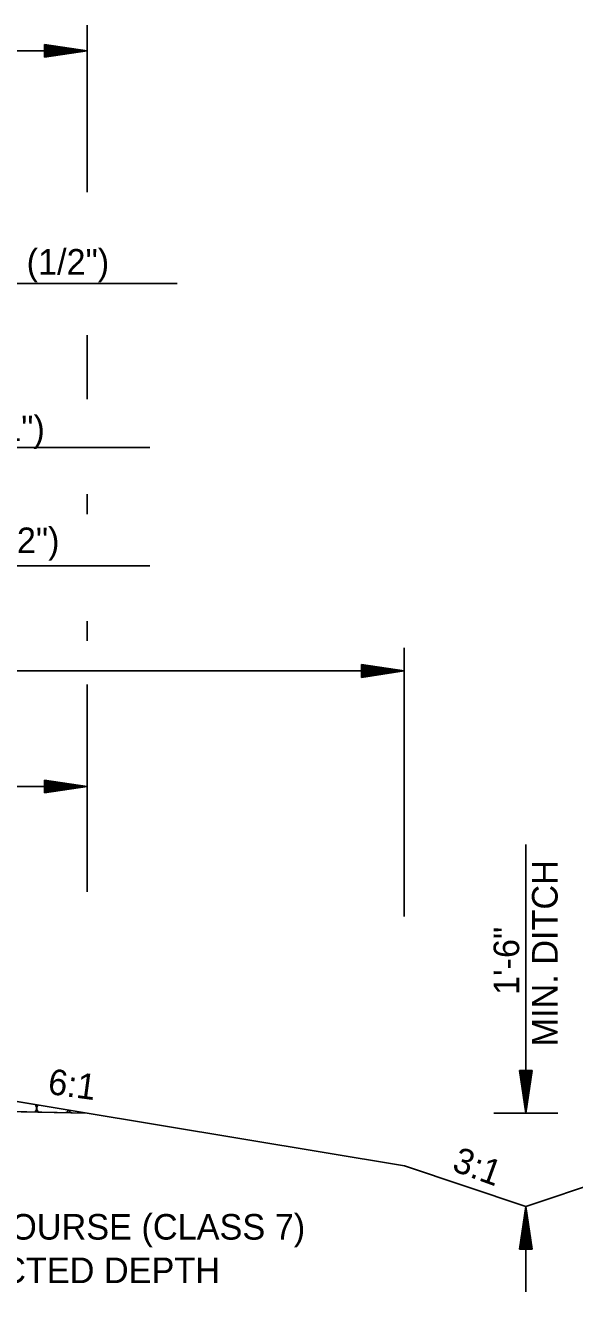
# Model space of a CAD drawing. Extents: x 1371763 to 1372860, y 385599 to 385872.
# Drawn here: x 1372116.52 to 1372129.38, y 385642.19 to 385671.88 of the extents above; entities that cross this region are included whole.
import ezdxf

# ---------------------------------------------------------------- set-up
doc = ezdxf.new("R2010")
doc.units = 0
doc.layers.add('R_Draft', color=7, linetype='Continuous')
doc.layers.add('R_Fin Surface', color=7, linetype='Continuous')

msp = doc.modelspace()

# ---------------------------------------------------------------- linework, layer by layer
at = {"layer": 'R_Draft'}
for p, q in [((1372117.962, 385667.967), (1372117.962, 385671.877)), ((1372048.826, 385671.277), (1372117.962, 385671.277)), ((1372116.962, 385671.427), (1372117.962, 385671.277)), ((1372116.962, 385671.427), (1372116.962, 385671.127)), ((1372116.962, 385671.402), (1372117.795, 385671.277)), ((1372116.962, 385671.376), (1372117.623, 385671.277)), ((1372116.962, 385671.351), (1372117.456, 385671.277)), ((1372116.962, 385671.325), (1372117.287, 385671.277)), ((1372116.962, 385671.3), (1372117.12, 385671.277)), ((1372116.962, 385671.127), (1372117.962, 385671.277)), ((1372116.962, 385671.228), (1372117.287, 385671.277)), ((1372116.962, 385671.177), (1372117.623, 385671.277)), ((1372116.962, 385671.152), (1372117.795, 385671.277)), ((1372116.962, 385671.202), (1372117.456, 385671.277)), ((1372116.962, 385671.253), (1372117.12, 385671.277)), ((1372120.069, 385665.821), (1372094.393, 385665.821)), ((1372117.962, 385663.113), (1372117.962, 385664.613)), ((1372119.435, 385661.977), (1372094.393, 385661.977)), ((1372117.962, 385660.416), (1372117.962, 385660.881)), ((1372119.435, 385659.202), (1372094.393, 385659.202)), ((1372117.962, 385657.442), (1372117.962, 385657.908)), ((1372125.391, 385650.981), (1372125.391, 385657.279)), ((1372101.391, 385656.739), (1372125.391, 385656.739)), ((1372124.391, 385656.889), (1372125.391, 385656.739)), ((1372124.391, 385656.889), (1372124.391, 385656.589)), ((1372124.391, 385656.864), (1372125.224, 385656.739)), ((1372124.391, 385656.838), (1372125.052, 385656.739)), ((1372124.391, 385656.813), (1372124.885, 385656.739)), ((1372124.391, 385656.787), (1372124.716, 385656.739)), ((1372124.391, 385656.762), (1372124.549, 385656.739)), ((1372124.391, 385656.589), (1372125.391, 385656.739)), ((1372124.391, 385656.69), (1372124.716, 385656.739)), ((1372124.391, 385656.639), (1372125.052, 385656.739)), ((1372124.391, 385656.614), (1372125.224, 385656.739)), ((1372124.391, 385656.664), (1372124.885, 385656.739)), ((1372124.391, 385656.715), (1372124.549, 385656.739)), ((1372117.962, 385651.56), (1372117.962, 385656.425)), ((1372109.39, 385654.032), (1372117.962, 385654.031)), ((1372116.962, 385654.181), (1372117.962, 385654.031)), ((1372116.962, 385653.881), (1372116.962, 385654.181)), ((1372116.962, 385654.156), (1372117.795, 385654.031)), ((1372116.962, 385654.131), (1372117.623, 385654.031)), ((1372116.962, 385654.106), (1372117.456, 385654.031)), ((1372116.962, 385654.08), (1372117.287, 385654.031)), ((1372116.962, 385654.055), (1372117.12, 385654.031)), ((1372116.962, 385653.881), (1372117.962, 385654.031)), ((1372116.962, 385653.983), (1372117.287, 385654.031)), ((1372116.962, 385653.932), (1372117.623, 385654.031)), ((1372116.962, 385653.906), (1372117.795, 385654.031)), ((1372116.962, 385653.957), (1372117.456, 385654.031)), ((1372116.962, 385654.008), (1372117.12, 385654.031)), ((1372128.239, 385646.373), (1372128.239, 385652.671)), ((1372109.393, 385647.801), (1372125.393, 385645.134)), ((1372128.089, 385647.373), (1372128.239, 385646.373)), ((1372128.389, 385647.373), (1372128.089, 385647.373)), ((1372128.114, 385647.373), (1372128.239, 385646.54)), ((1372128.14, 385647.373), (1372128.239, 385646.712)), ((1372128.165, 385647.373), (1372128.239, 385646.878)), ((1372128.19, 385647.373), (1372128.239, 385647.048)), ((1372128.216, 385647.373), (1372128.239, 385647.215)), ((1372128.389, 385647.373), (1372128.239, 385646.373)), ((1372128.288, 385647.373), (1372128.239, 385647.048)), ((1372128.339, 385647.373), (1372128.239, 385646.712)), ((1372128.364, 385647.373), (1372128.239, 385646.54)), ((1372128.314, 385647.373), (1372128.239, 385646.878)), ((1372128.263, 385647.373), (1372128.239, 385647.215)), ((1372094.393, 385646.844), (1372117.962, 385646.373)), ((1372127.489, 385646.373), (1372128.989, 385646.373)), ((1372128.089, 385643.185), (1372128.239, 385644.185)), ((1372128.114, 385643.185), (1372128.239, 385644.018)), ((1372128.389, 385643.185), (1372128.239, 385644.185)), ((1372128.239, 385642.185), (1372128.239, 385644.185)), ((1372128.364, 385643.185), (1372128.239, 385644.018)), ((1372128.14, 385643.185), (1372128.239, 385643.846)), ((1372128.165, 385643.185), (1372128.239, 385643.68)), ((1372128.339, 385643.185), (1372128.239, 385643.846)), ((1372128.314, 385643.185), (1372128.239, 385643.68)), ((1372128.191, 385643.185), (1372128.239, 385643.51)), ((1372128.216, 385643.185), (1372128.239, 385643.343)), ((1372128.288, 385643.185), (1372128.239, 385643.51)), ((1372128.263, 385643.185), (1372128.239, 385643.343)), ((1372128.089, 385643.185), (1372128.389, 385643.185))]:
    msp.add_line(p, q, dxfattribs=at)
msp.add_lwpolyline([(1372094.393, 385646.844), (1372094.393, 385647.344), (1372101.856, 385647.195), (1372101.688, 385647.531), (1372101.562, 385647.784), (1372101.477, 385647.952), (1372109.393, 385647.636), (1372109.393, 385647.801), (1372117.962, 385646.373)], close=True, dxfattribs=at)
for centre, start_param, end_param in [((1372116.407, 385646.485), 0.342438, 0.494577), ((1372116.407, 385646.485), 5.815936, 6.625624), ((1372117.157, 385646.485), 2.721243, 3.618325), ((1372117.157, 385646.485), 5.729255, 6.080831), ((1372117.907, 385646.485), 3.35836, 3.709502)]:
    msp.add_ellipse(centre, major_axis=(0.375, 0), ratio=0.517889, start_param=start_param, end_param=end_param, dxfattribs=at)
at = {"layer": 'R_Fin Surface'}
for p, q in [((1372128.239, 385644.185), (1372132.983, 385645.766)), ((1372125.393, 385645.134), (1372128.239, 385644.185))]:
    msp.add_line(p, q, dxfattribs=at)

# ---------------------------------------------------------------- texts
at = {"layer": 'R_Draft'}
for s, rotation, p in [('7\'-1 1/2" ACHM SURFACE COURSE (1/2")', 0, (1372103.089, 385666.031)), ('7\'-2 3/4" ACHM BINDER COURSE (1")', 0, (1372103.053, 385662.127)), ('7\'-4 1/2" ACHM BASE COURSE (1 1/2")', 360, (1372102.949, 385659.502)), ('MIN. DITCH', 90, (1372128.983, 385647.935)), ('1\'-6"', 90, (1372128.083, 385649.142)), ('6:1', 352.2846, (1372117.023, 385646.825)), ('3:1', 340.0022, (1372126.482, 385645.032)), ('AGGREGATE BASE COURSE (CLASS 7)', 360, (1372107.912, 385643.406)), ('VAR. COMPACTED DEPTH', 360, (1372110.912, 385642.386))]:
    msp.add_text(s, height=0.6, rotation=rotation, dxfattribs=at).set_placement(p)

doc.saveas('drawing.dxf')
